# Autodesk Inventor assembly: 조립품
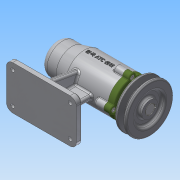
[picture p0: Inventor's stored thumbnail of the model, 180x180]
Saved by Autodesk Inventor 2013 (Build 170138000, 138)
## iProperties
Created: 2019-07
Part Number: 조립품
Document SubType Name: Assembly
Designer: Administrator
Author: Administrator
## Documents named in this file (12)
- C:\Users\Administrator\Desktop\490704V1024\답안조립품.iam
- C:\Users\Administrator\Desktop\490704V1024\본체.ipt
- C:\Users\Administrator\Desktop\490704V1024\V벨트풀리.ipt
- C:\Users\Administrator\Desktop\490704V1024\멈춤나사 M3.ipt
- C:\Users\Administrator\Desktop\490704V1024\베어링 6004.ipt
- C:\Users\Administrator\Desktop\490704V1024\베어링 51202.ipt
- C:\Users\Administrator\Desktop\490704V1024\볼트 M4.ipt
- C:\Users\Administrator\Desktop\490704V1024\어댑터슬리브.ipt
- C:\Users\Administrator\Desktop\490704V1024\오일 실.ipt
- C:\Users\Administrator\Desktop\490704V1024\축.ipt
- C:\Users\Administrator\Desktop\490704V1024\커버.ipt
- C:\Users\Administrator\Desktop\490704V1024\키 5 x 5 x 16.ipt
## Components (1 placed, 1 different names)
1. V벨트풀리:1
